(* Logix 5000 project; controller CompactLogix vendor 1 type 14 code 65 rev 13.1; software revision 13.03 *)
// Sample Ladder Logic for MVI69-MNETC.

TASK MainTask (continuous, watchdog 500 ms) : MainProgram

MODULES
   Controller : vendor 1 type 14 code 65 (CompactLogixL35Controller 0, rev 13.1)
      LocalENB : 1769-L35E Ethernet Port (CompactLogixL35Ethernet 1, rev 13.1)
      Local : CompactBus (CompactVirtualAdapter 3, rev 13.1, Input RPI 2 ms)
         MNETC : 1769-MODULE (Compact 1, rev 1.1, Output RPI 2 ms)
END_MODULES

TYPE MNetCBlockStats :   // This object is used to store the block transfer statistics for the MVI69-MNetC module.
STRUCT
   Read : INT;   // Total number of read block transfers
   Write : INT;   // Total number of write block transfers
   Parse : INT;   // Total number of blocks parsed
   Event : INT;   // Total number of event blocks received
   Cmd : INT;   // Total number of command blocks received
   Err : INT;   // Total number of block transfer errors
END_STRUCT
END_TYPE

TYPE MnetCCmdControl :
STRUCT
   CmdCntReqClientID : INT;   // Command Control Request Client IDentification by Index number 0 to 29
   CmdCntReqCMDqty : INT;   // Command Control Request command quantity
   CmdCntReqCMDindex : INT[16];   // Contains index in the command list for the 1st command to be entered into Command queue
   WriteCmdBits : INT[30];   // This is for 30 Clients with 16 commands each.
   CmdBitsTrigger : BOOL;   // Activates the Selected Write Command Bits
END_STRUCT
END_TYPE

TYPE MNetCCONFIG :
STRUCT
   BlockTransferSize : INT;   // Determines Register quantity to move across the Backplane
END_STRUCT
END_TYPE

TYPE MNetCConnectionInput :
STRUCT
   Data : INT[62];   // Block Transfer Array Size [62] or [122] or [242]
END_STRUCT
END_TYPE

TYPE MNetCConnectionOutput :
STRUCT
   Data : INT[61];   // Block Transfer Array Size [61] or [121] or [241]
END_STRUCT
END_TYPE

TYPE MNetCCONTROL :
STRUCT
   BootTimer : TIMER;
   ColdBoot : BOOL;   // Hardware reset of the Module
   WarmBoot : BOOL;   // Configuration data reset in the Module.
   EventCmd : MNetCEventCmd[1];
   EventCmdTrigger : BOOL;
   EventCmdPending : BOOL;   // Halts rung until Module is ready.
   CmdControl : MnetCCmdControl;
   CmdControlPending : BOOL;   // Halts rung until Module is ready.
   CmdControlTrigger : BOOL;
   IPAdressControl : MNetCIPAddress;
   CmdBitPending : BOOL;   // Halts rung until Module is ready.
   CmdBitTrigger : BOOL;
END_STRUCT
END_TYPE

TYPE MNetCDATA :
STRUCT
   ReadData : INT[480];   // Read Database Table array size. This array size should match the array size in the module.
   WriteData : INT[480];   // Write Database Table array size. This array size should match the array size in the module.
END_STRUCT
END_TYPE

TYPE MNetCEventCmd :   // Data structure to use for Event message generation.
STRUCT
   IP0 : INT;   // TCP/IP-0 address for MNETC module
   IP1 : INT;   // TCP/IP-1 address for MNETC module
   IP2 : INT;   // TCP/IP-2 address for MNETC module
   IP3 : INT;   // TCP/IP-3 address for MNETC module
   ServPort : INT;   // TCP Service Port number (0-65535), 502 for MBAP, 2000 for MNET
   Node : INT;   // Modbus slave node address (0 to 247)
   DBAddress : INT;   // Module internal database to use with message
   Count : INT;   // Register or data point count
   Swap : INT;   // Swap code to use with functions 3 and 4
   Function : INT;   // Modbus function code for message
   Address : INT;   // Address to interface with in device
   EvntCmdClientID : INT;   // Block2000 Client IDentification by Index number 0 to 29
END_STRUCT
END_TYPE

TYPE MNetCInitOutData :   // Used to bring the Module into a known state after a restart operation.
STRUCT
   InitOutBlkIDLim : INT;   // Block Index Limit for ReadData size of the array
END_STRUCT
END_TYPE

TYPE MNetCIPAddress :   // Dynamicaly Alterable TCP/IP address for MNETC module. Block 9990 and 9991
STRUCT
   GetIPAddress : BOOL;   // Gets IP address
   GetIP : INT[4];   // Get IP
   GetIPAddressPending : BOOL;   // Halts rung until Module is ready.
   SetIPAddress : BOOL;   // Sets IP address
   SetIP : INT[4];   // Set IP
   SetIPAddrPending : BOOL;   // Halts rung until Module is ready.
   WriteIPAddressAck : INT[4];   // Module's response to Setting IP Address
END_STRUCT
END_TYPE

TYPE MNetCIPAddress1 :   // Dynamicaly Alterable TCP/IP address for MNETC module. Block 9990 and 9991
STRUCT
   GetIPAddress : BOOL;   // Gets IP address
   GetIP : INT[4];   // Get IP
   GetIPAddressPending : BOOL;   // Halts rung until Module is ready.
   SetIPAddress : BOOL;   // Sets IP address
   SetIP : INT[4];   // Set IP
   SetIPAddrPending : BOOL;   // Halts rung until Module is ready.
   WriteIPAddressAck : INT[4];   // Module's response to Setting IP Address
END_STRUCT
END_TYPE

TYPE MNetCModuleDef :
STRUCT
   CONFIG : MNetCCONFIG;
   DATA : MNetCDATA;
   CONTROL : MNetCCONTROL;
   STATUS : MNetCSTATUS;
   UTIL : MNetCUTIL;
END_STRUCT
END_TYPE

TYPE MNetCPortStats :   // This object is used to store the port statistics for an MVI69-MNet port.
STRUCT
   CmdReq : INT;   // Total number of command list requests sent
   CmdResp : INT;   // Total number of command list responses received
   CmdErr : INT;   // Total number of command list errors
   Requests : INT;   // Total number of requests for port
   Responses : INT;   // Total number of responses for port
   ErrSent : INT;   // Total number of errors sent
   ErrRec : INT;   // Total number of errors received
   CfgErrWord : INT;   // Configuration Error Word
   CurErr : INT;   // Current Error code
   LastErr : INT;   // Last recorded error code
END_STRUCT
END_TYPE

TYPE MNetCSTATUS :   // This status data is returned on each read block and can be used to detect proper module operation.
STRUCT
   PassCnt : INT;   // Program cycle counter
   Block : MNetCBlockStats;   // Block transfer statistics
   MnetServer : MNetCPortStats;   // MNet server status data
   MBAPServer : MNetCPortStats;   // MBAP server status data
   StatReqClientID : INT;   // Status Request Client IDentification by Index number 0 to 29
   CmdBits : INT[30];
   ClientStats : MNetCPortStats[30];   // Client status data
   ClientStatsPending : BOOL;   // Halts rung until Module is ready.
   ClientStatsTrigger : BOOL;   // Get Client Status
   CmdErrorList : INT[16];   // Cmd Error List
END_STRUCT
END_TYPE

TYPE MNetCUTIL :
STRUCT
   ReadDataSizeGet : INT;   // Gets ReadData Array Length.
   WriteDataSizeGet : INT;   // Gets WriteData Array Length.
   ReadDataBlkCount : INT;   // holds the value of the Block Counts of the Read Data Array.
   WriteDataBlkCount : INT;   // holds the value of the Block Counts of the Write Data Array.
   RBTSremainder : INT;   // The remainder of the 60, 120 or 240 block to transfer.
   WBTSremainder : INT;   // The remainder of the 60, 120 or 240 block to transfer.
   LastRead : INT;   // Index of last read block
   LastWrite : INT;   // Index of last write block
   BlockIndex : INT;   // Computed block offset for data table
   StatusIndex : INT;   // Computed block offset for status data
   InitOutputData : MNetCInitOutData;
END_STRUCT
END_TYPE

VAR_GLOBAL   (* controller tags *)
   MNetC : MNetCModuleDef;
        .BP.LASTREAD   // this tag receives Block ID data from the last scan.
        .GETIPADDRESS   // Gets the IP address from the Module.
        .SETIPADDRESS   // Sets the IP address for the Module
END_VAR

PROGRAM MainProgram   (* routine attr 65 MainRoutine *)

ROUTINE MainRoutine   (* ladder *)
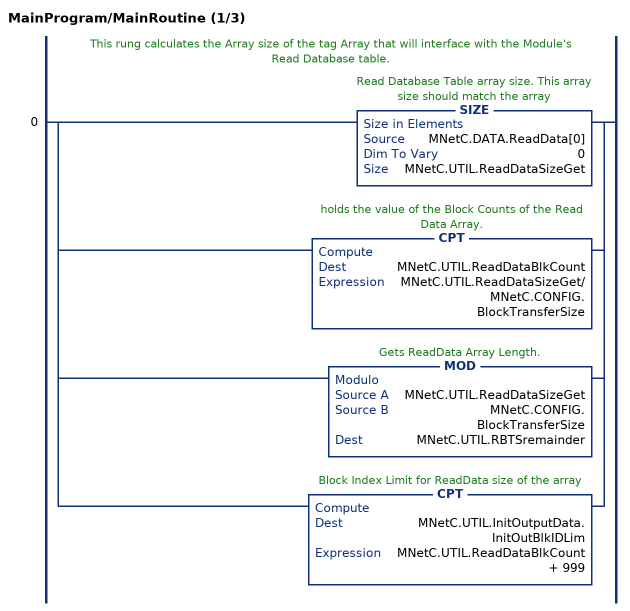
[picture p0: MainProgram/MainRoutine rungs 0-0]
   // This rung calculates the Array size of the tag Array that will interface with the Module's Read Database table.
   0: [SIZE(MNetC.DATA.ReadData[0],0,MNetC.UTIL.ReadDataSizeGet) ,CPT(MNetC.UTIL.ReadDataBlkCount,MNetC.UTIL.ReadDataSizeGet/MNetC.CONFIG.BlockTransferSize) ,MOD(MNetC.UTIL.ReadDataSizeGet,MNetC.CONFIG.BlockTransferSize,MNetC.UTIL.RBTSremainder) ,CPT(MNetC.UTIL.InitOutputData.InitOutBlkIDLim,MNetC.UTIL.ReadDataBlkCount + 999) ];
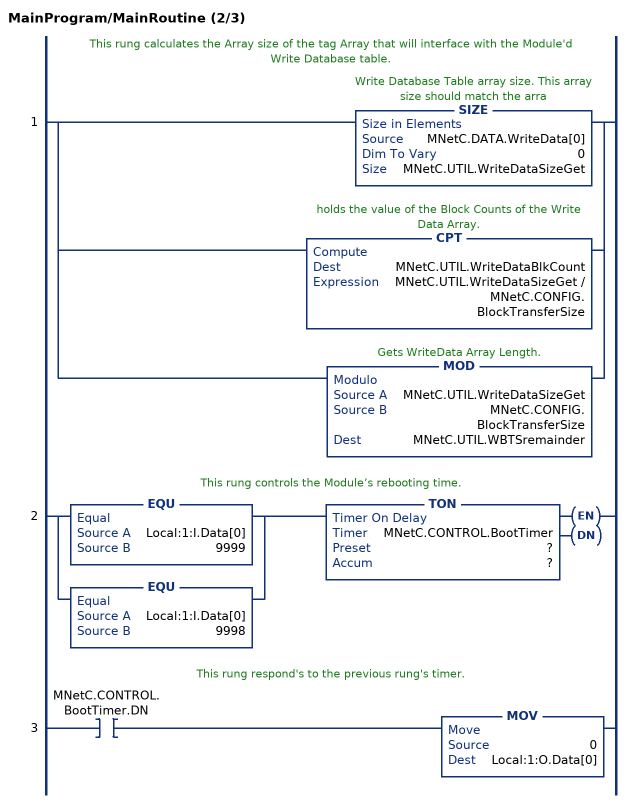
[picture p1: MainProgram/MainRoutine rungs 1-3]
   // This rung calculates the Array size of the tag Array that will interface with the Module'd Write Database table.
   1: [SIZE(MNetC.DATA.WriteData[0],0,MNetC.UTIL.WriteDataSizeGet) ,CPT(MNetC.UTIL.WriteDataBlkCount,MNetC.UTIL.WriteDataSizeGet / MNetC.CONFIG.BlockTransferSize) ,MOD(MNetC.UTIL.WriteDataSizeGet,MNetC.CONFIG.BlockTransferSize,MNetC.UTIL.WBTSremainder) ];
   // This rung controls the Module’s rebooting time.
   2: [EQU(Local:1:I.Data[0],9999) ,EQU(Local:1:I.Data[0],9998) ]TON(MNetC.CONTROL.BootTimer,?,?);
   // This rung respond's to the previous rung's timer.
   3: XIC(MNetC.CONTROL.BootTimer.DN)MOV(0,Local:1:O.Data[0]);
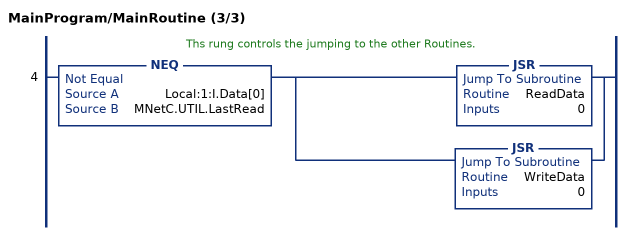
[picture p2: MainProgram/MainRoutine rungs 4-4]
   // Ths rung controls the jumping to the other Routines.
   4: NEQ(Local:1:I.Data[0],MNetC.UTIL.LastRead)[JSR(ReadData,0) ,JSR(WriteData,0) ];
END_ROUTINE

ROUTINE ReadData   (* ladder *)
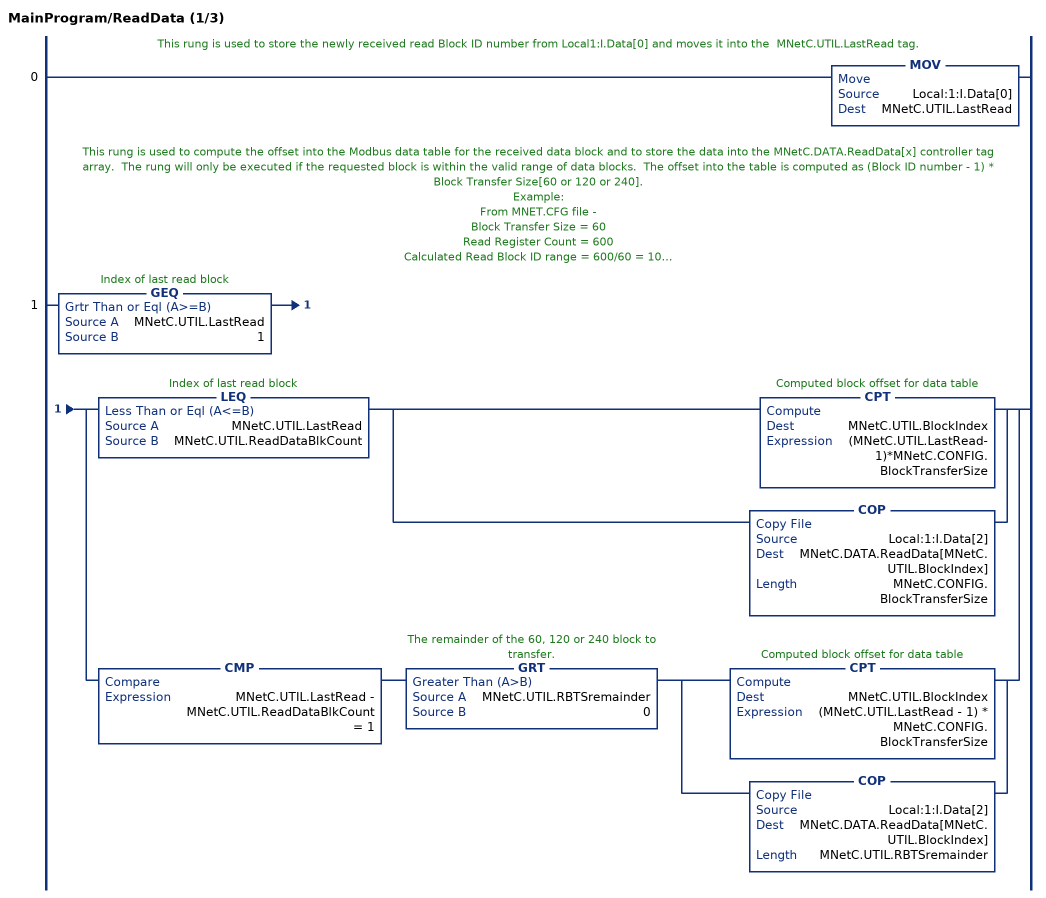
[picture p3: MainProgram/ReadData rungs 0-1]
   // This rung is used to store the newly received read Block ID number from Local1:I.Data[0] and moves it into the  MNetC.UTIL.LastRead tag.
   0: MOV(Local:1:I.Data[0],MNetC.UTIL.LastRead);
   // This rung is used to compute the offset into the Modbus data table for the received data block and to store the data into the MNetC.DATA.ReadData[x] controller tag array.  The rung will only be executed if the requested block is within the valid range of data blocks.  The offset into the table is computed as (Block ID number - 1) * Block Transfer Size[60 or 120 or 240].
   // Example:
   // From MNET.CFG file -
   //    Block Transfer Size = 60
   //    Read Register Count = 600
   // 	Calculated Read Block ID range = 600/60 = 10.
   // 	Expected Read Block ID will range from 1 to 10
   // Set the High Limit in the LIM function to the integer value of Read Register Count: divided by Block Transfer Size:
   1: GEQ(MNetC.UTIL.LastRead,1)[LEQ(MNetC.UTIL.LastRead,MNetC.UTIL.ReadDataBlkCount) [CPT(MNetC.UTIL.BlockIndex,(MNetC.UTIL.LastRead-1)*MNetC.CONFIG.BlockTransferSize) ,COP(Local:1:I.Data[2],MNetC.DATA.ReadData[MNetC.UTIL.BlockIndex],MNetC.CONFIG.BlockTransferSize) ] ,CMP(MNetC.UTIL.LastRead - MNetC.UTIL.ReadDataBlkCount = 1) GRT(MNetC.UTIL.RBTSremainder,0) [CPT(MNetC.UTIL.BlockIndex,(MNetC.UTIL.LastRead - 1) * MNetC.CONFIG.BlockTransferSize) ,COP(Local:1:I.Data[2],MNetC.DATA.ReadData[MNetC.UTIL.BlockIndex],MNetC.UTIL.RBTSremainder) ] ];
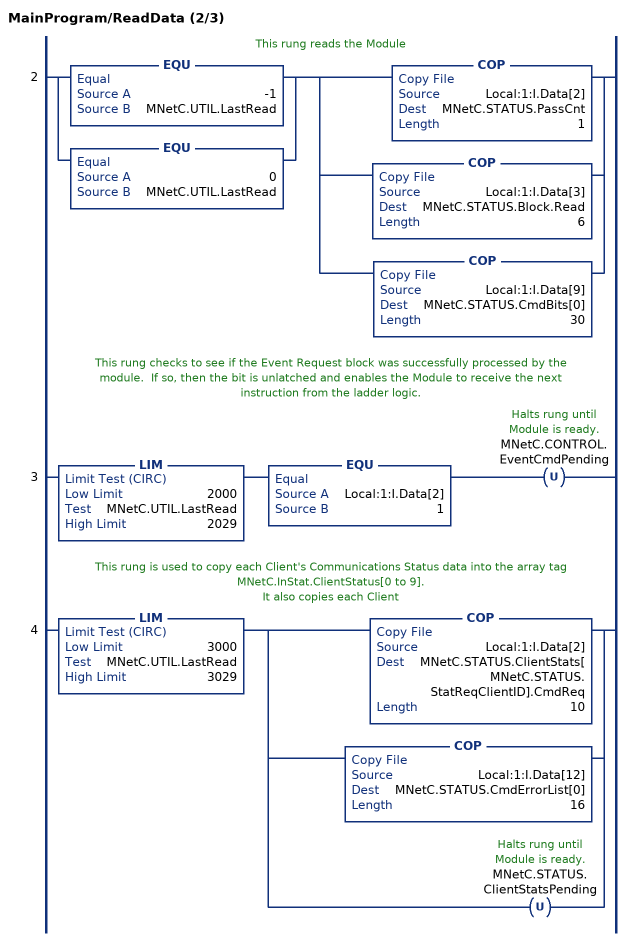
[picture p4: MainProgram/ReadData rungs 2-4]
   // This rung reads the Module
   2: [EQU(-1,MNetC.UTIL.LastRead) ,EQU(0,MNetC.UTIL.LastRead) ][COP(Local:1:I.Data[2],MNetC.STATUS.PassCnt,1) ,COP(Local:1:I.Data[3],MNetC.STATUS.Block.Read,6) ,COP(Local:1:I.Data[9],MNetC.STATUS.CmdBits[0],30) ];
   // This rung checks to see if the Event Request block was successfully processed by the module.  If so, then the bit is unlatched and enables the Module to receive the next instruction from the ladder logic.
   3: LIM(2000,MNetC.UTIL.LastRead,2029)EQU(Local:1:I.Data[2],1)OTU(MNetC.CONTROL.EventCmdPending);
   // This rung is used to copy each Client's Communications Status data into the array tag MNetC.InStat.ClientStatus[0 to 9].
   // It also copies each Client
   4: LIM(3000,MNetC.UTIL.LastRead,3029)[COP(Local:1:I.Data[2],MNetC.STATUS.ClientStats[MNetC.STATUS.StatReqClientID].CmdReq,10) ,COP(Local:1:I.Data[12],MNetC.STATUS.CmdErrorList[0],16) ,OTU(MNetC.STATUS.ClientStatsPending) ];
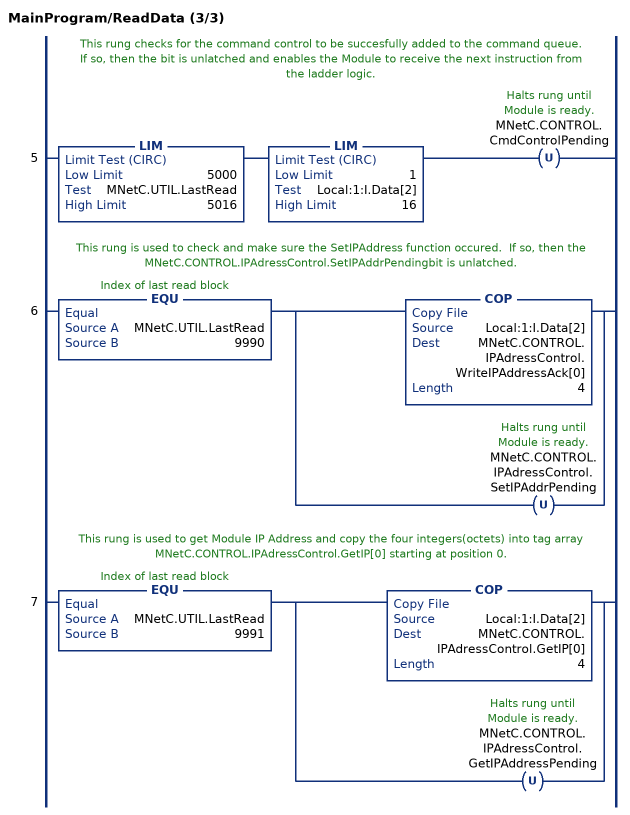
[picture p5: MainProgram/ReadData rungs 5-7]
   // This rung checks for the command control to be succesfully added to the command queue.  If so, then the bit is unlatched and enables the Module to receive the next instruction from the ladder logic.
   5: LIM(5000,MNetC.UTIL.LastRead,5016)LIM(1,Local:1:I.Data[2],16)OTU(MNetC.CONTROL.CmdControlPending);
   // This rung is used to check and make sure the SetIPAddress function occured.  If so, then the MNetC.CONTROL.IPAdressControl.SetIPAddrPendingbit is unlatched.
   6: EQU(MNetC.UTIL.LastRead,9990)[COP(Local:1:I.Data[2],MNetC.CONTROL.IPAdressControl.WriteIPAddressAck[0],4) ,OTU(MNetC.CONTROL.IPAdressControl.SetIPAddrPending) ];
   // This rung is used to get Module IP Address and copy the four integers(octets) into tag array MNetC.CONTROL.IPAdressControl.GetIP[0] starting at position 0.
   7: EQU(MNetC.UTIL.LastRead,9991)[COP(Local:1:I.Data[2],MNetC.CONTROL.IPAdressControl.GetIP[0],4) ,OTU(MNetC.CONTROL.IPAdressControl.GetIPAddressPending) ];
END_ROUTINE

ROUTINE WriteData   (* ladder *)
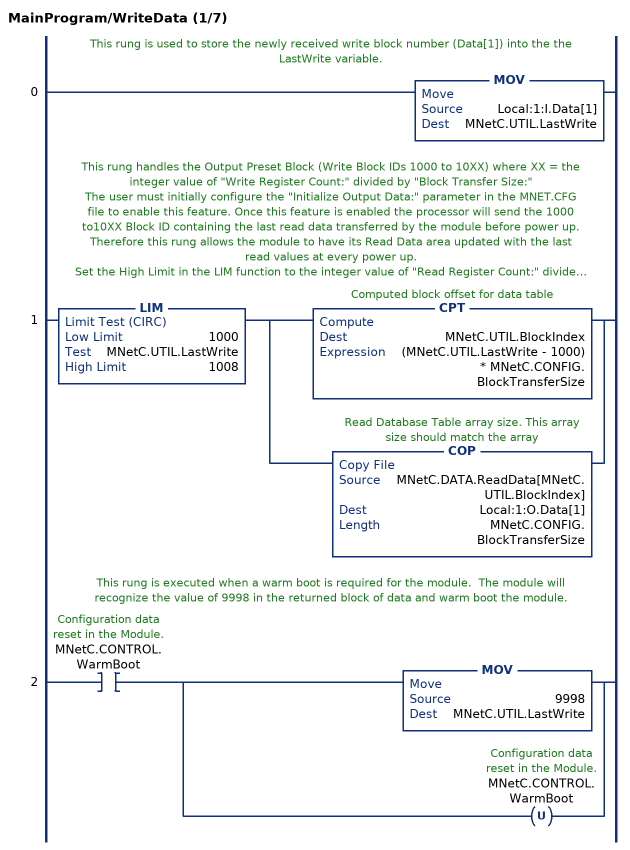
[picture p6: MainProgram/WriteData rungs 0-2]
   // This rung is used to store the newly received write block number (Data[1]) into the the LastWrite variable.
   0: MOV(Local:1:I.Data[1],MNetC.UTIL.LastWrite);
   // This rung handles the Output Preset Block (Write Block IDs 1000 to 10XX) where XX = the integer value of "Write Register Count:" divided by "Block Transfer Size:"
   // The user must initially configure the "Initialize Output Data:" parameter in the MNET.CFG file to enable this feature. Once this feature is enabled the processor will send the 1000 to10XX Block ID containing the last read data transferred by the module before power up. Therefore this rung allows the module to have its Read Data area updated with the last read values at every power up.
   // Set the High Limit in the LIM function to the integer value of "Read Register Count:" divided by "Block Transfer Size:" plus 1000. Set the Low Limit to 1000.
   1: LIM(1000,MNetC.UTIL.LastWrite,1008)[CPT(MNetC.UTIL.BlockIndex,(MNetC.UTIL.LastWrite - 1000) * MNetC.CONFIG.BlockTransferSize) ,COP(MNetC.DATA.ReadData[MNetC.UTIL.BlockIndex],Local:1:O.Data[1],MNetC.CONFIG.BlockTransferSize) ];
   // This rung is executed when a warm boot is required for the module.  The module will recognize the value of 9998 in the returned block of data and warm boot the module.
   2: XIC(MNetC.CONTROL.WarmBoot)[MOV(9998,MNetC.UTIL.LastWrite) ,OTU(MNetC.CONTROL.WarmBoot) ];
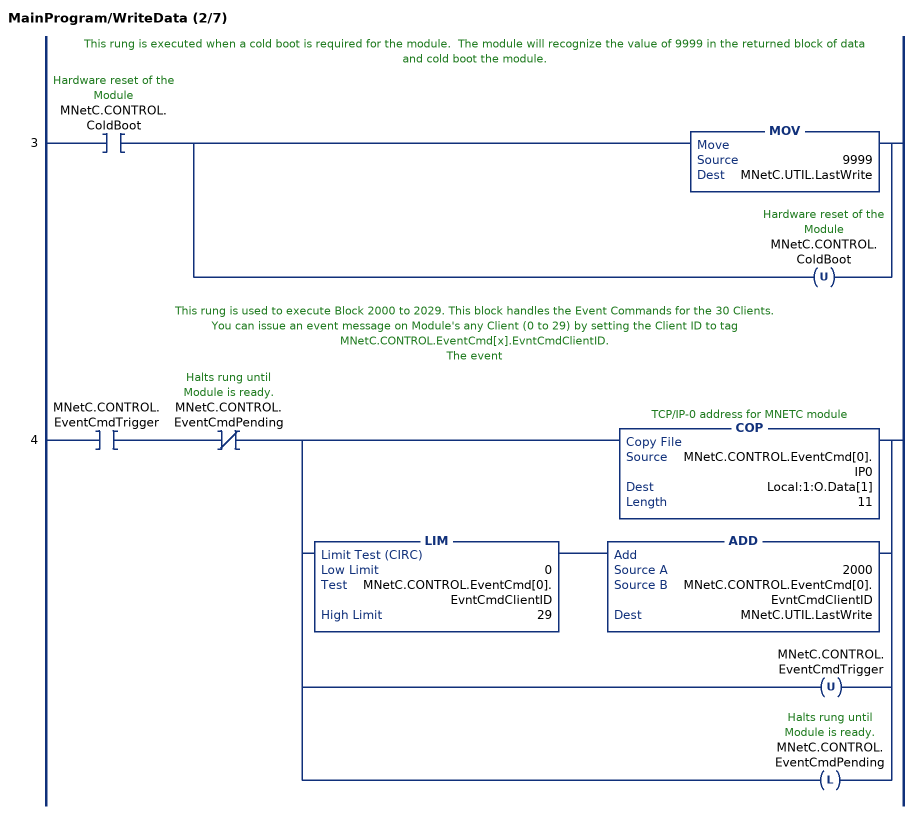
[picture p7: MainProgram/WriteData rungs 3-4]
   // This rung is executed when a cold boot is required for the module.  The module will recognize the value of 9999 in the returned block of data and cold boot the module.
   3: XIC(MNetC.CONTROL.ColdBoot)[MOV(9999,MNetC.UTIL.LastWrite) ,OTU(MNetC.CONTROL.ColdBoot) ];
   // This rung is used to execute Block 2000 to 2029. This block handles the Event Commands for the 30 Clients.
   // You can issue an event message on Module's any Client (0 to 29) by setting the Client ID to tag MNetC.CONTROL.EventCmd[x].EvntCmdClientID.
   // The event
   4: XIC(MNetC.CONTROL.EventCmdTrigger)XIO(MNetC.CONTROL.EventCmdPending)[COP(MNetC.CONTROL.EventCmd[0].IP0,Local:1:O.Data[1],11) ,LIM(0,MNetC.CONTROL.EventCmd[0].EvntCmdClientID,29) ADD(2000,MNetC.CONTROL.EventCmd[0].EvntCmdClientID,MNetC.UTIL.LastWrite) ,OTU(MNetC.CONTROL.EventCmdTrigger) ,OTL(MNetC.CONTROL.EventCmdPending) ];
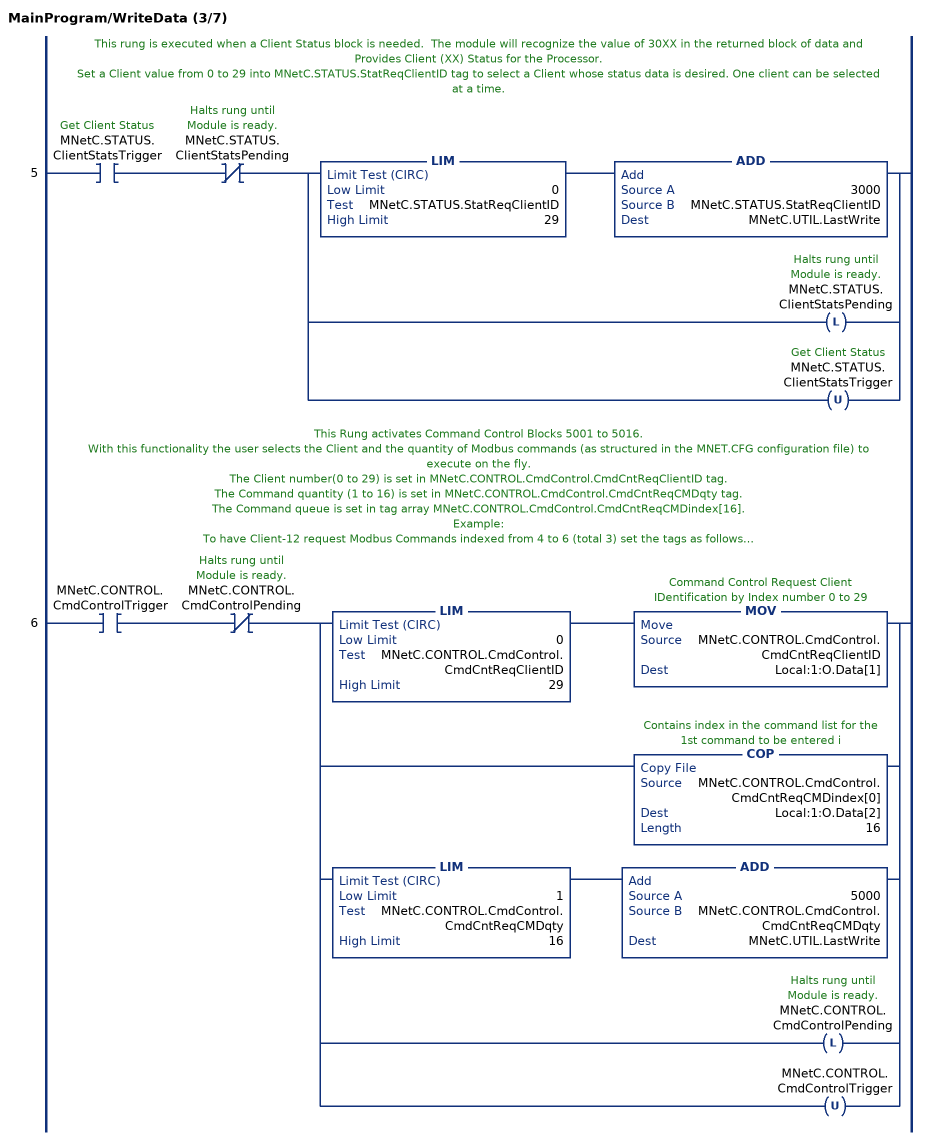
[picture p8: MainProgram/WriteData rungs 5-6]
   // This rung is executed when a Client Status block is needed.  The module will recognize the value of 30XX in the returned block of data and Provides Client (XX) Status for the Processor.
   // Set a Client value from 0 to 29 into MNetC.STATUS.StatReqClientID tag to select a Client whose status data is desired. One client can be selected at a time.
   5: XIC(MNetC.STATUS.ClientStatsTrigger)XIO(MNetC.STATUS.ClientStatsPending)[LIM(0,MNetC.STATUS.StatReqClientID,29) ADD(3000,MNetC.STATUS.StatReqClientID,MNetC.UTIL.LastWrite) ,OTL(MNetC.STATUS.ClientStatsPending) ,OTU(MNetC.STATUS.ClientStatsTrigger) ];
   // This Rung activates Command Control Blocks 5001 to 5016.
   // With this functionality the user selects the Client and the quantity of Modbus commands (as structured in the MNET.CFG configuration file) to execute on the fly.
   // The Client number(0 to 29) is set in MNetC.CONTROL.CmdControl.CmdCntReqClientID tag.
   // The Command quantity (1 to 16) is set in MNetC.CONTROL.CmdControl.CmdCntReqCMDqty tag.
   // The Command queue is set in tag array MNetC.CONTROL.CmdControl.CmdCntReqCMDindex[16].
   // Example:
   // To have Client-12 request Modbus Commands indexed from 4 to 6 (total 3) set the tags as follows:
   // MNetC.CONTROL.CmdControl.CmdCntReqClientID = 12
   // MNetC.CONTROL.CmdControl.CmdCntReqCMDqty = 3
   // MNetC.CONTROL.CmdControl.CmdCntReqCMDindex[0] = 4
   // MNetC.CONTROL.CmdControl.CmdCntReqCMDindex[1] = 5
   // MNetC.CONTROL.CmdControl.CmdCntReqCMDindex[2] = 6
   6: XIC(MNetC.CONTROL.CmdControlTrigger)XIO(MNetC.CONTROL.CmdControlPending)[LIM(0,MNetC.CONTROL.CmdControl.CmdCntReqClientID,29) MOV(MNetC.CONTROL.CmdControl.CmdCntReqClientID,Local:1:O.Data[1]) ,COP(MNetC.CONTROL.CmdControl.CmdCntReqCMDindex[0],Local:1:O.Data[2],16) ,LIM(1,MNetC.CONTROL.CmdControl.CmdCntReqCMDqty,16) ADD(5000,MNetC.CONTROL.CmdControl.CmdCntReqCMDqty,MNetC.UTIL.LastWrite) ,OTL(MNetC.CONTROL.CmdControlPending) ,OTU(MNetC.CONTROL.CmdControlTrigger) ];
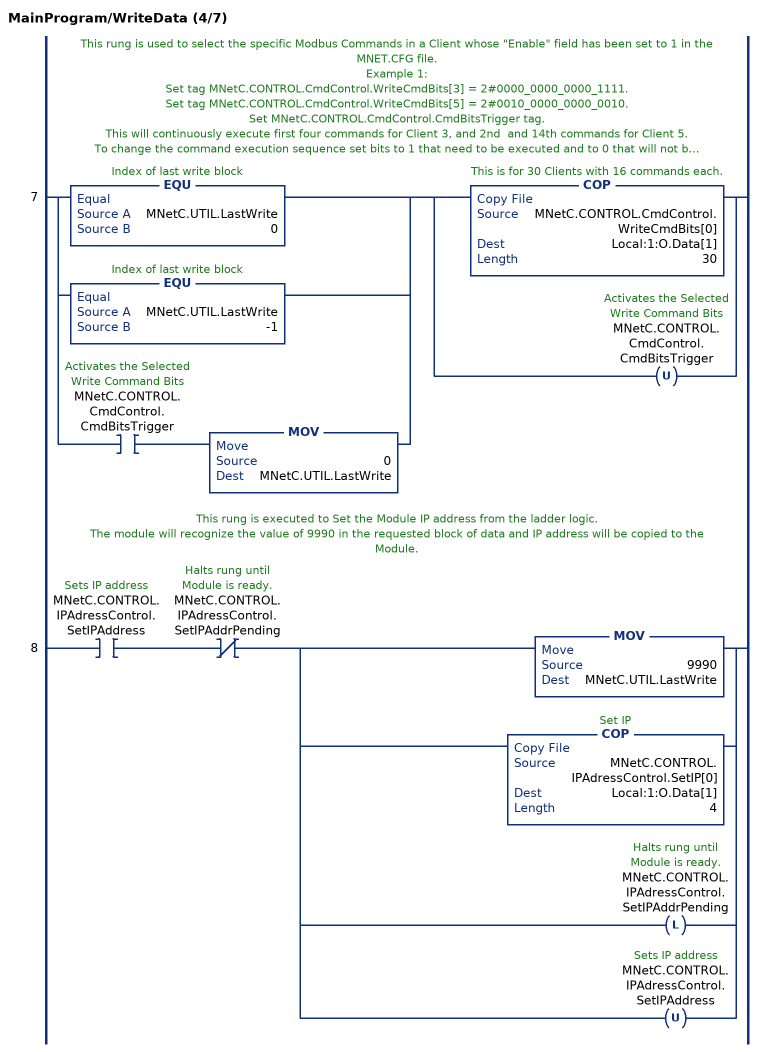
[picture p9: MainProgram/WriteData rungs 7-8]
   // This rung is used to select the specific Modbus Commands in a Client whose "Enable" field has been set to 1 in the MNET.CFG file.
   // Example 1:
   // Set tag MNetC.CONTROL.CmdControl.WriteCmdBits[3] = 2#0000_0000_0000_1111.
   // Set tag MNetC.CONTROL.CmdControl.WriteCmdBits[5] = 2#0010_0000_0000_0010.
   // Set MNetC.CONTROL.CmdControl.CmdBitsTrigger tag.
   // This will continuously execute first four commands for Client 3, and 2nd  and 14th commands for Client 5.
   // To change the command execution sequence set bits to 1 that need to be executed and to 0 that will not be executed.
   // Example 2:
   // Set tag MNetC.CONTROL.CmdControl.WriteCmdBits[11] = 2#0010_0100_0010_0001.
   // Set MNetC.CONTROL.CmdControl.CmdBitsTrigger tag.
   // This will continuously execute 1st, 6th, 11th and 14th commands for Client 11.
   // NOTE-0: All the Modbus Commands for Clients 3, 5 and 11 in the MNET.CFG file must also be enabled, but only the once set as in the examples will be continuously executed.
   7: [EQU(MNetC.UTIL.LastWrite,0) ,EQU(MNetC.UTIL.LastWrite,-1) ,XIC(MNetC.CONTROL.CmdControl.CmdBitsTrigger) MOV(0,MNetC.UTIL.LastWrite) ][COP(MNetC.CONTROL.CmdControl.WriteCmdBits[0],Local:1:O.Data[1],30) ,OTU(MNetC.CONTROL.CmdControl.CmdBitsTrigger) ];
   // This rung is executed to Set the Module IP address from the ladder logic.
   //  The module will recognize the value of 9990 in the requested block of data and IP address will be copied to the Module.
   8: XIC(MNetC.CONTROL.IPAdressControl.SetIPAddress)XIO(MNetC.CONTROL.IPAdressControl.SetIPAddrPending)[MOV(9990,MNetC.UTIL.LastWrite) ,COP(MNetC.CONTROL.IPAdressControl.SetIP[0],Local:1:O.Data[1],4) ,OTL(MNetC.CONTROL.IPAdressControl.SetIPAddrPending) ,OTU(MNetC.CONTROL.IPAdressControl.SetIPAddress) ];
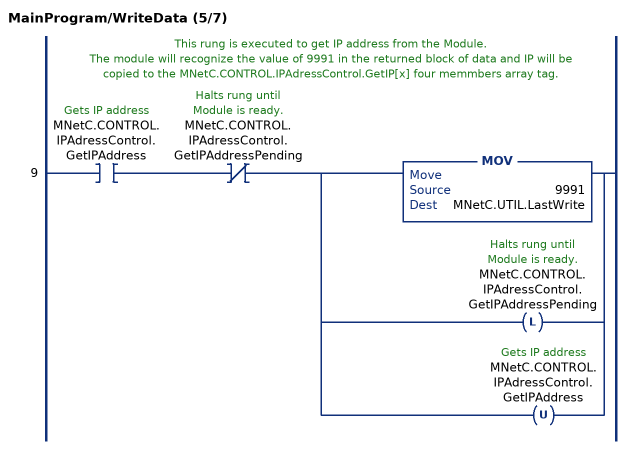
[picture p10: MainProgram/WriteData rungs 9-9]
   // This rung is executed to get IP address from the Module.
   //  The module will recognize the value of 9991 in the returned block of data and IP will be copied to the MNetC.CONTROL.IPAdressControl.GetIP[x] four memmbers array tag.
   9: XIC(MNetC.CONTROL.IPAdressControl.GetIPAddress)XIO(MNetC.CONTROL.IPAdressControl.GetIPAddressPending)[MOV(9991,MNetC.UTIL.LastWrite) ,OTL(MNetC.CONTROL.IPAdressControl.GetIPAddressPending) ,OTU(MNetC.CONTROL.IPAdressControl.GetIPAddress) ];
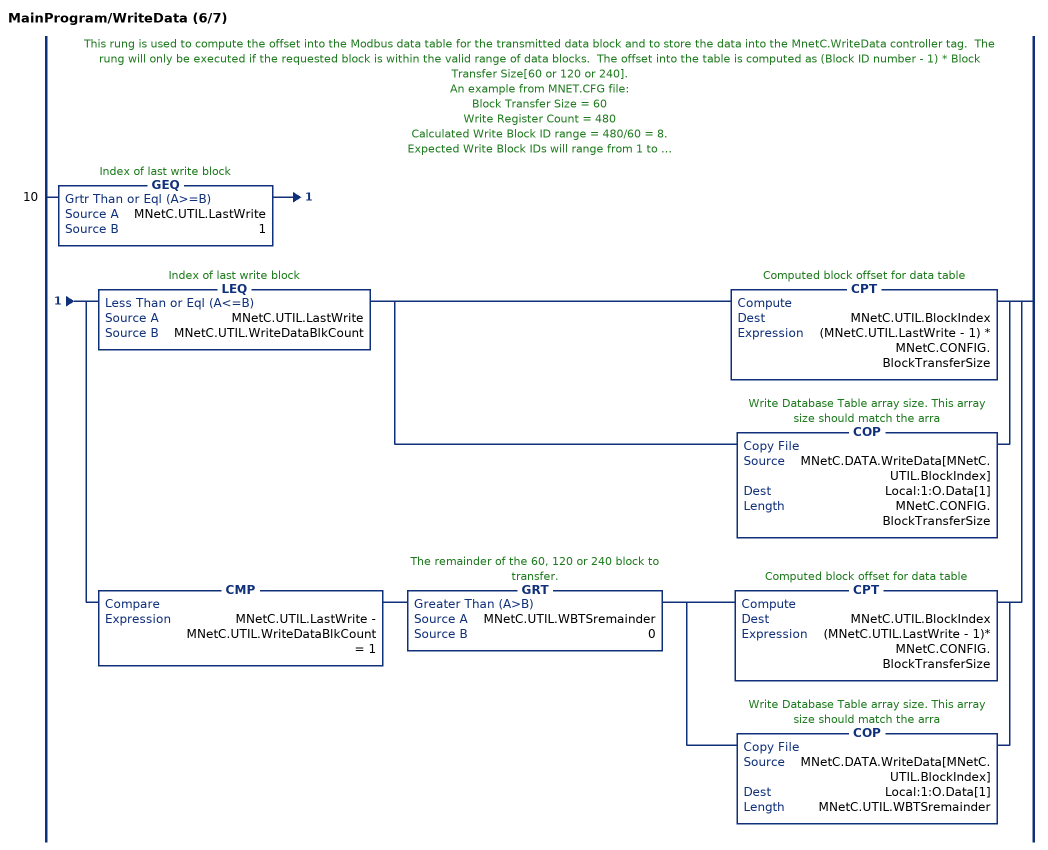
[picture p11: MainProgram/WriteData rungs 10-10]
   // This rung is used to compute the offset into the Modbus data table for the transmitted data block and to store the data into the MnetC.WriteData controller tag.  The rung will only be executed if the requested block is within the valid range of data blocks.  The offset into the table is computed as (Block ID number - 1) * Block Transfer Size[60 or 120 or 240].
   // An example from MNET.CFG file:
   // 	Block Transfer Size = 60
   // 	Write Register Count = 480
   // 	Calculated Write Block ID range = 480/60 = 8.
   // 	Expected Write Block IDs will range from 1 to 8
   // Set the High Limit in the LIM function to the integer value of "Write Register Count:" divided by "Block Transfer Size:" Set the Low Limit always to 1.
   10: GEQ(MNetC.UTIL.LastWrite,1)[LEQ(MNetC.UTIL.LastWrite,MNetC.UTIL.WriteDataBlkCount) [CPT(MNetC.UTIL.BlockIndex,(MNetC.UTIL.LastWrite - 1) * MNetC.CONFIG.BlockTransferSize) ,COP(MNetC.DATA.WriteData[MNetC.UTIL.BlockIndex],Local:1:O.Data[1],MNetC.CONFIG.BlockTransferSize) ] ,CMP(MNetC.UTIL.LastWrite - MNetC.UTIL.WriteDataBlkCount = 1) GRT(MNetC.UTIL.WBTSremainder,0) [CPT(MNetC.UTIL.BlockIndex,(MNetC.UTIL.LastWrite - 1)* MNetC.CONFIG.BlockTransferSize) ,COP(MNetC.DATA.WriteData[MNetC.UTIL.BlockIndex],Local:1:O.Data[1],MNetC.UTIL.WBTSremainder) ] ];
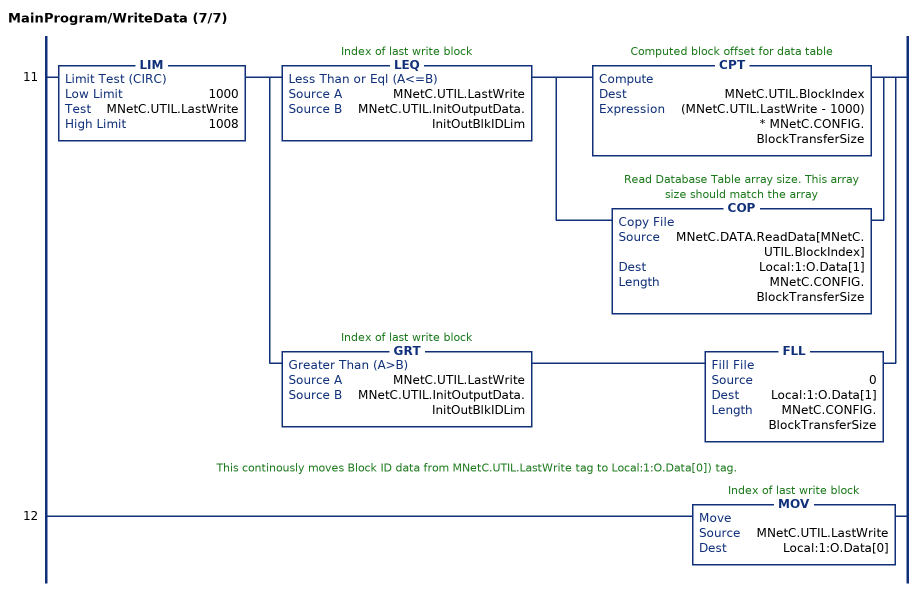
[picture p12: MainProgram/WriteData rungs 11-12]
   11: LIM(1000,MNetC.UTIL.LastWrite,1008)[LEQ(MNetC.UTIL.LastWrite,MNetC.UTIL.InitOutputData.InitOutBlkIDLim) [CPT(MNetC.UTIL.BlockIndex,(MNetC.UTIL.LastWrite - 1000) * MNetC.CONFIG.BlockTransferSize) ,COP(MNetC.DATA.ReadData[MNetC.UTIL.BlockIndex],Local:1:O.Data[1],MNetC.CONFIG.BlockTransferSize) ] ,GRT(MNetC.UTIL.LastWrite,MNetC.UTIL.InitOutputData.InitOutBlkIDLim) FLL(0,Local:1:O.Data[1],MNetC.CONFIG.BlockTransferSize) ];
   // This continously moves Block ID data from MNetC.UTIL.LastWrite tag to Local:1:O.Data[0]) tag.
   12: MOV(MNetC.UTIL.LastWrite,Local:1:O.Data[0]);
END_ROUTINE
END_PROGRAM
